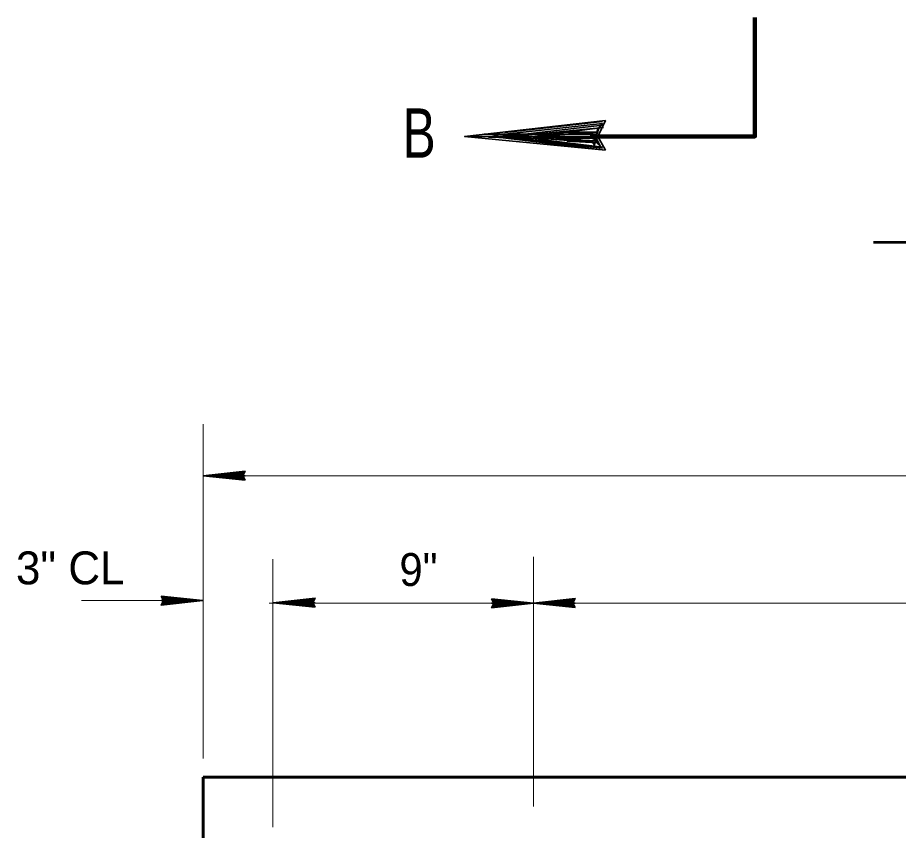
# Model space of a CAD drawing. Extents: x 4.49 to 7.69, y 0.28 to 2.27.
# Drawn here: x 4.8263 to 5.0493, y 1.4646 to 1.6705 of the extents above; entities that cross this region are included whole.
import ezdxf
from ezdxf.enums import TextEntityAlignment as Align

# ---------------------------------------------------------------- set-up
doc = ezdxf.new("R2010")
doc.units = 0
doc.header["$LTSCALE"] = 0.0033
doc.layers.add('1', color=7, linetype='Continuous', lineweight=35)

msp = doc.modelspace()

# ---------------------------------------------------------------- linework, layer by layer
at = {"layer": '1'}
for p, q in [((4.974417, 1.644167), (4.949667, 1.641417)), ((4.974417, 1.643667), (4.949667, 1.641)), ((4.974417, 1.64325), (4.949667, 1.640417)), ((4.974667, 1.642667), (4.94975, 1.64025)), ((4.975167, 1.640417), (4.9395, 1.640417)), ((4.974417, 1.637667), (4.947833, 1.641)), ((4.974417, 1.637667), (4.947833, 1.640417)), ((4.974417, 1.637), (4.947833, 1.64025)), ((4.974417, 1.637), (4.947833, 1.64025)), ((4.974417, 1.637417), (4.947833, 1.64025)), ((4.883917, 1.554417), (4.873333, 1.554417)), ((4.883667, 1.553583), (4.875833, 1.554583)), ((4.883667, 1.553583), (4.875833, 1.554417)), ((4.883667, 1.553417), (4.875833, 1.554333)), ((4.883667, 1.553417), (4.875833, 1.554333)), ((4.883667, 1.5535), (4.875833, 1.554333)), ((4.883667, 1.5555), (4.876333, 1.554667)), ((4.883667, 1.555333), (4.876333, 1.554583)), ((4.883667, 1.55525), (4.876333, 1.554417)), ((4.88375, 1.555083), (4.876417, 1.554333)), ((4.862917, 1.523833), (4.87075, 1.522917)), ((4.862917, 1.523833), (4.87075, 1.522917)), ((4.862917, 1.52375), (4.87075, 1.522917)), ((4.862917, 1.523667), (4.87075, 1.522833)), ((4.862917, 1.523667), (4.87075, 1.522667)), ((4.901417, 1.523333), (4.894083, 1.5225)), ((4.901417, 1.523167), (4.894083, 1.522417)), ((4.901417, 1.523083), (4.894083, 1.52225)), ((4.946583, 1.523167), (4.954417, 1.52225)), ((4.946583, 1.523167), (4.954417, 1.52225)), ((4.946583, 1.523083), (4.954417, 1.52225)), ((4.96725, 1.52325), (4.959917, 1.522417)), ((4.96725, 1.523083), (4.959917, 1.522333)), ((4.862667, 1.522833), (4.87325, 1.522833)), ((4.862833, 1.522167), (4.870167, 1.522917)), ((4.862917, 1.522), (4.87025, 1.522833)), ((4.862917, 1.521917), (4.87025, 1.522667)), ((4.862917, 1.52175), (4.87025, 1.522583)), ((4.901667, 1.52225), (4.891083, 1.52225)), ((4.901417, 1.521417), (4.893583, 1.522417)), ((4.901417, 1.521417), (4.893583, 1.52225)), ((4.901417, 1.52125), (4.893583, 1.522167)), ((4.901417, 1.52125), (4.893583, 1.522167)), ((4.901417, 1.521333), (4.893583, 1.522167)), ((4.9015, 1.522917), (4.894167, 1.522167)), ((4.946333, 1.522167), (4.956917, 1.522167)), ((4.9465, 1.5215), (4.953833, 1.52225)), ((4.946583, 1.523), (4.954417, 1.522167)), ((4.946583, 1.523), (4.954417, 1.522)), ((4.946583, 1.521333), (4.953917, 1.522167)), ((4.946583, 1.52125), (4.953917, 1.522)), ((4.946583, 1.521083), (4.953917, 1.521917)), ((4.9675, 1.522167), (4.956917, 1.522167)), ((4.96725, 1.521333), (4.959417, 1.522333)), ((4.96725, 1.521333), (4.959417, 1.522167)), ((4.96725, 1.521167), (4.959417, 1.522083)), ((4.96725, 1.521167), (4.959417, 1.522083)), ((4.96725, 1.52125), (4.959417, 1.522083)), ((4.96725, 1.523), (4.959917, 1.522167)), ((4.967333, 1.522833), (4.96, 1.522083))]:
    msp.add_line(p, q, dxfattribs=at)
at = {"layer": '1', "lineweight": 53}
msp.add_line((5.043, 1.613583), (5.315667, 1.613583), dxfattribs=at)
at = {"layer": '1', "lineweight": 13}
for p, q in [((4.873333, 1.482833), (4.873333, 1.5675)), ((4.87325, 1.554417), (5.455583, 1.554417)), ((4.891, 1.465417), (4.891, 1.533333)), ((4.956917, 1.470667), (4.956917, 1.533917)), ((4.8425, 1.522833), (4.863333, 1.522833)), ((4.89, 1.522167), (5.436917, 1.522167)), ((4.873333, 1.478083), (4.873333, 1.478167))]:
    msp.add_line(p, q, dxfattribs=at)
at = {"layer": '1', "lineweight": 60}
msp.add_line((4.873333, 1.478083), (5.456667, 1.478083), dxfattribs=at)
at = {"layer": '1', "lineweight": 90}
msp.add_lwpolyline([(5.013, 1.6705), (5.013, 1.640417), (4.971333, 1.640417)], dxfattribs=at)
at = {"layer": '1'}
for points in [[(4.975167, 1.636917), (4.9395, 1.640417), (4.975167, 1.644417), (4.97325, 1.640417)], [(4.97275, 1.64025), (4.956917, 1.639917), (4.956917, 1.64025), (4.959917, 1.64025), (4.97275, 1.639917), (4.9625, 1.639667), (4.97325, 1.63925), (4.9655, 1.639167), (4.97325, 1.63875), (4.961417, 1.639667), (4.945583, 1.64025), (4.948667, 1.641), (4.9445, 1.641), (4.97275, 1.641), (4.964417, 1.6415), (4.97325, 1.6415), (4.95525, 1.64025), (4.97325, 1.6425)], [(4.883917, 1.553333), (4.873333, 1.554417), (4.883917, 1.555583), (4.883333, 1.554417)], [(4.883167, 1.554333), (4.8785, 1.55425), (4.8785, 1.554333), (4.879417, 1.554333), (4.883167, 1.55425), (4.880167, 1.554167), (4.883333, 1.554083), (4.881083, 1.554), (4.883333, 1.553917), (4.879833, 1.554167), (4.875167, 1.554333), (4.876083, 1.554583), (4.874833, 1.554583), (4.883167, 1.554583), (4.88075, 1.55475), (4.883333, 1.55475), (4.878, 1.554333), (4.883333, 1.555)], [(4.862667, 1.523917), (4.87325, 1.522833), (4.862667, 1.521667), (4.86325, 1.522833)], [(4.863417, 1.522917), (4.868083, 1.523), (4.868083, 1.522917), (4.867167, 1.522917), (4.863417, 1.523), (4.866417, 1.523083), (4.86325, 1.523167), (4.8655, 1.52325), (4.86325, 1.523333), (4.86675, 1.523083), (4.871417, 1.522917), (4.8705, 1.522667), (4.87175, 1.522667), (4.863417, 1.522667), (4.865833, 1.5225), (4.86325, 1.5225), (4.868583, 1.522917), (4.86325, 1.52225)], [(4.901667, 1.521167), (4.891083, 1.52225), (4.901667, 1.523417), (4.901083, 1.52225)], [(4.946333, 1.52325), (4.956917, 1.522167), (4.946333, 1.521), (4.946917, 1.522167)], [(4.9675, 1.521083), (4.956917, 1.522167), (4.9675, 1.523333), (4.966917, 1.522167)], [(4.900917, 1.522167), (4.89625, 1.522083), (4.89625, 1.522167), (4.897167, 1.522167), (4.900917, 1.522083), (4.897917, 1.522), (4.901083, 1.521917), (4.898833, 1.521833), (4.901083, 1.52175), (4.897583, 1.522), (4.892917, 1.522167), (4.893833, 1.522417), (4.892583, 1.522417), (4.900917, 1.522417), (4.8985, 1.522583), (4.901083, 1.522583), (4.89575, 1.522167), (4.901083, 1.522833)], [(4.947083, 1.52225), (4.95175, 1.522333), (4.95175, 1.52225), (4.950833, 1.52225), (4.947083, 1.522333), (4.950083, 1.522417), (4.946917, 1.5225), (4.949167, 1.522583), (4.946917, 1.522667), (4.950417, 1.522417), (4.955083, 1.52225), (4.954167, 1.522), (4.955417, 1.522), (4.947083, 1.522), (4.9495, 1.521833), (4.946917, 1.521833), (4.95225, 1.52225), (4.946917, 1.521583)], [(4.96675, 1.522083), (4.962083, 1.522), (4.962083, 1.522083), (4.963, 1.522083), (4.96675, 1.522), (4.96375, 1.521917), (4.966917, 1.521833), (4.964667, 1.52175), (4.966917, 1.521667), (4.963417, 1.521917), (4.95875, 1.522083), (4.959667, 1.522333), (4.958417, 1.522333), (4.96675, 1.522333), (4.964333, 1.5225), (4.966917, 1.5225), (4.961583, 1.522083), (4.966917, 1.52275)]]:
    msp.add_lwpolyline(points, close=True, dxfattribs=at)
for points in [[(4.97275, 1.64025), (4.974, 1.637667), (4.97325, 1.6385), (4.97275, 1.639667), (4.97175, 1.63925), (4.972417, 1.638167), (4.972917, 1.64075), (4.9735, 1.6425), (4.974417, 1.64375)], [(4.883167, 1.554333), (4.883583, 1.553583), (4.883333, 1.553833), (4.883167, 1.554167), (4.882917, 1.554083), (4.883083, 1.55375), (4.88325, 1.5545), (4.883417, 1.555), (4.883667, 1.555417)], [(4.863417, 1.522917), (4.863, 1.523667), (4.86325, 1.523417), (4.863417, 1.523083), (4.863667, 1.523167), (4.8635, 1.5235), (4.863333, 1.52275), (4.863167, 1.52225), (4.862917, 1.521833)], [(4.900917, 1.522167), (4.901333, 1.521417), (4.901083, 1.521667), (4.900917, 1.522), (4.900667, 1.521917), (4.900833, 1.521583), (4.901, 1.522333), (4.901167, 1.522833), (4.901417, 1.52325)], [(4.96675, 1.522083), (4.967167, 1.521333), (4.966917, 1.521583), (4.96675, 1.521917), (4.9665, 1.521833), (4.966667, 1.5215), (4.966833, 1.52225), (4.967, 1.52275), (4.96725, 1.523167)], [(4.947083, 1.52225), (4.946667, 1.523), (4.946917, 1.52275), (4.947083, 1.522417), (4.947333, 1.5225), (4.947167, 1.522833), (4.947, 1.522083), (4.946833, 1.521583), (4.946583, 1.521167)]]:
    msp.add_lwpolyline(points, dxfattribs=at)
at = {"layer": '1', "lineweight": 60}
msp.add_lwpolyline([(5.456667, 1.478083), (5.456667, 1.311417), (4.873333, 1.311417), (4.873333, 1.478083)], dxfattribs=at)

# ---------------------------------------------------------------- texts
at = {"layer": '1', "width": 0.75}
msp.add_text('B', height=0.0125, dxfattribs=at).set_placement((4.923833, 1.635))
at = {"layer": '1'}
msp.add_text('3" CL', height=0.008334, dxfattribs=at).set_placement((4.825917, 1.526917))
at = {"layer": '1', "width": 0.95}
msp.add_text('9"', height=0.008334, dxfattribs=at).set_placement((4.927833, 1.5265), align=Align.CENTER)

doc.saveas('drawing.dxf')
